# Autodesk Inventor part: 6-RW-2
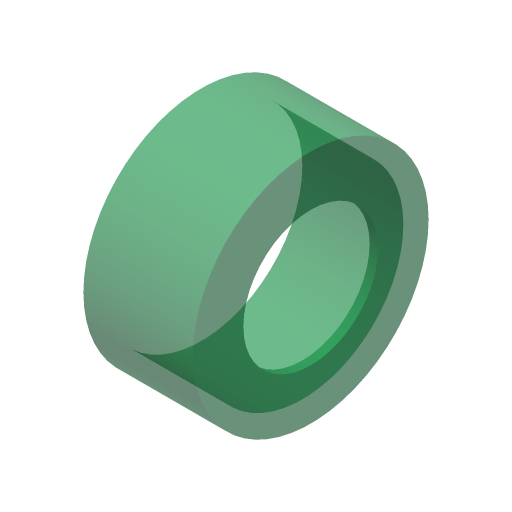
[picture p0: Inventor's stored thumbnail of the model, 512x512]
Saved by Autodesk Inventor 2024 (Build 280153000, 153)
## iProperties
Company: ATC
Created: 2023-03
Part Number: 6-RW-2
Document SubType Name: Modeling
Designer: Andrzej Jaskulski
Manufacturer: Standard
Standards Organization: Custom
Density: 1 g/cm^3
Material: Ogólny
Appearance: Przezroczyste - zielone 1
Checked By: A.J.
Engr Approved By: Andrzej Jaskulski
Mfg Approved By: Andrzej Jaskulski
Authority: A.J.
Title: A.J.: Kurs R2024-MEP
Author: Andrzej Jaskulski
Revision Number: 1/24
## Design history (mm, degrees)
sketch "Szkic1"
  geometry: C1 r 4 at (0, 0) reference; C2 r 6 at (0, 0) reference; C3 r 7 at (0, 0)
  constraints: 1 centre point, 1 coincident
  dimensions: "d4" = 1 radial gap between concentric circles of C3 C2
extrude "Wyciągnięcie proste1" new body sketch "Szkic1" distance "d0" = 6; taper "d1" = 0 deg
extrude "Wyciągnięcie proste2" join sketch "Szkic1" distance "d2" = 0.5; taper "d3" = 0 deg
node "Bryła1"
node "Korpusy bryłowe"
node "Korpusy powierzchniowe"
